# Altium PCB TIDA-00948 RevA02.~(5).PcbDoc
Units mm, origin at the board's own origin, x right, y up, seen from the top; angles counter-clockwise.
Board outline 125.73 x 87.63 mm, 2 copper layers (Top Layer, Bottom Layer), stack 1.575 mm thick; 30 components, 8 nets, 44 pads, 0 vias.
Unrouted connection lines stored in the file: 2.
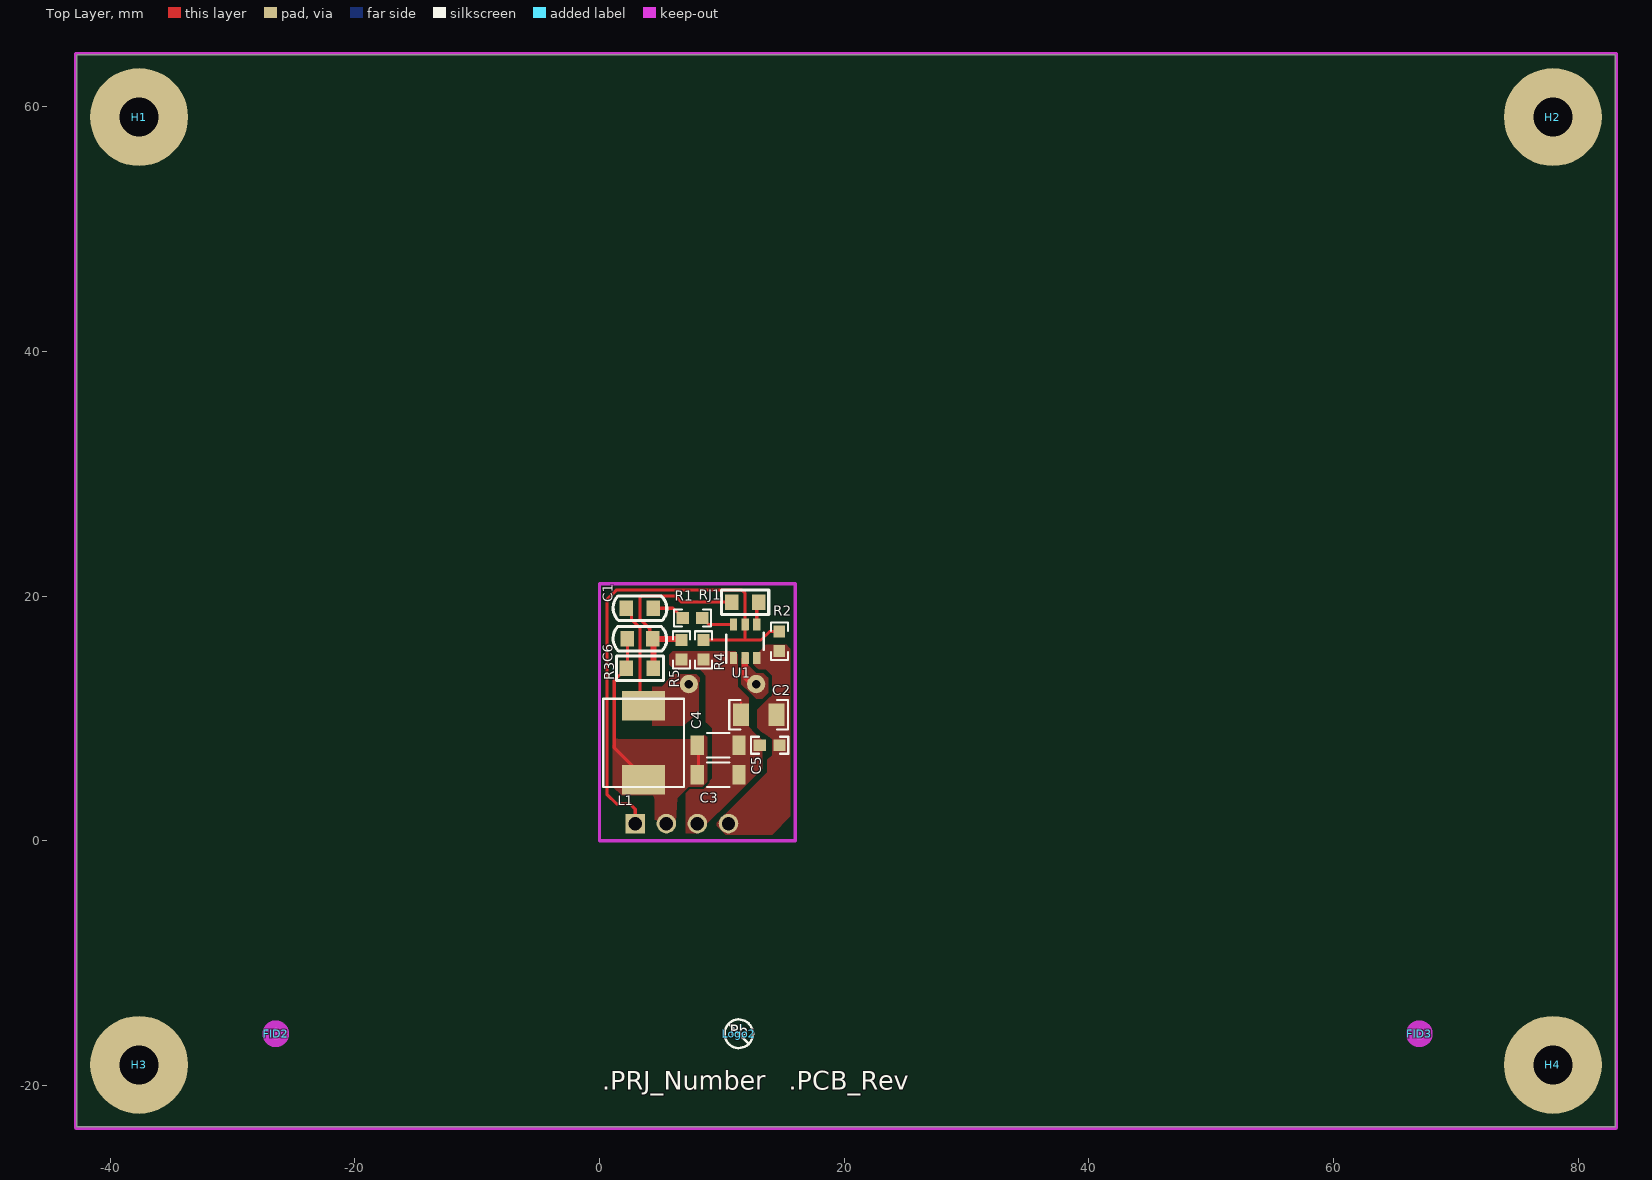
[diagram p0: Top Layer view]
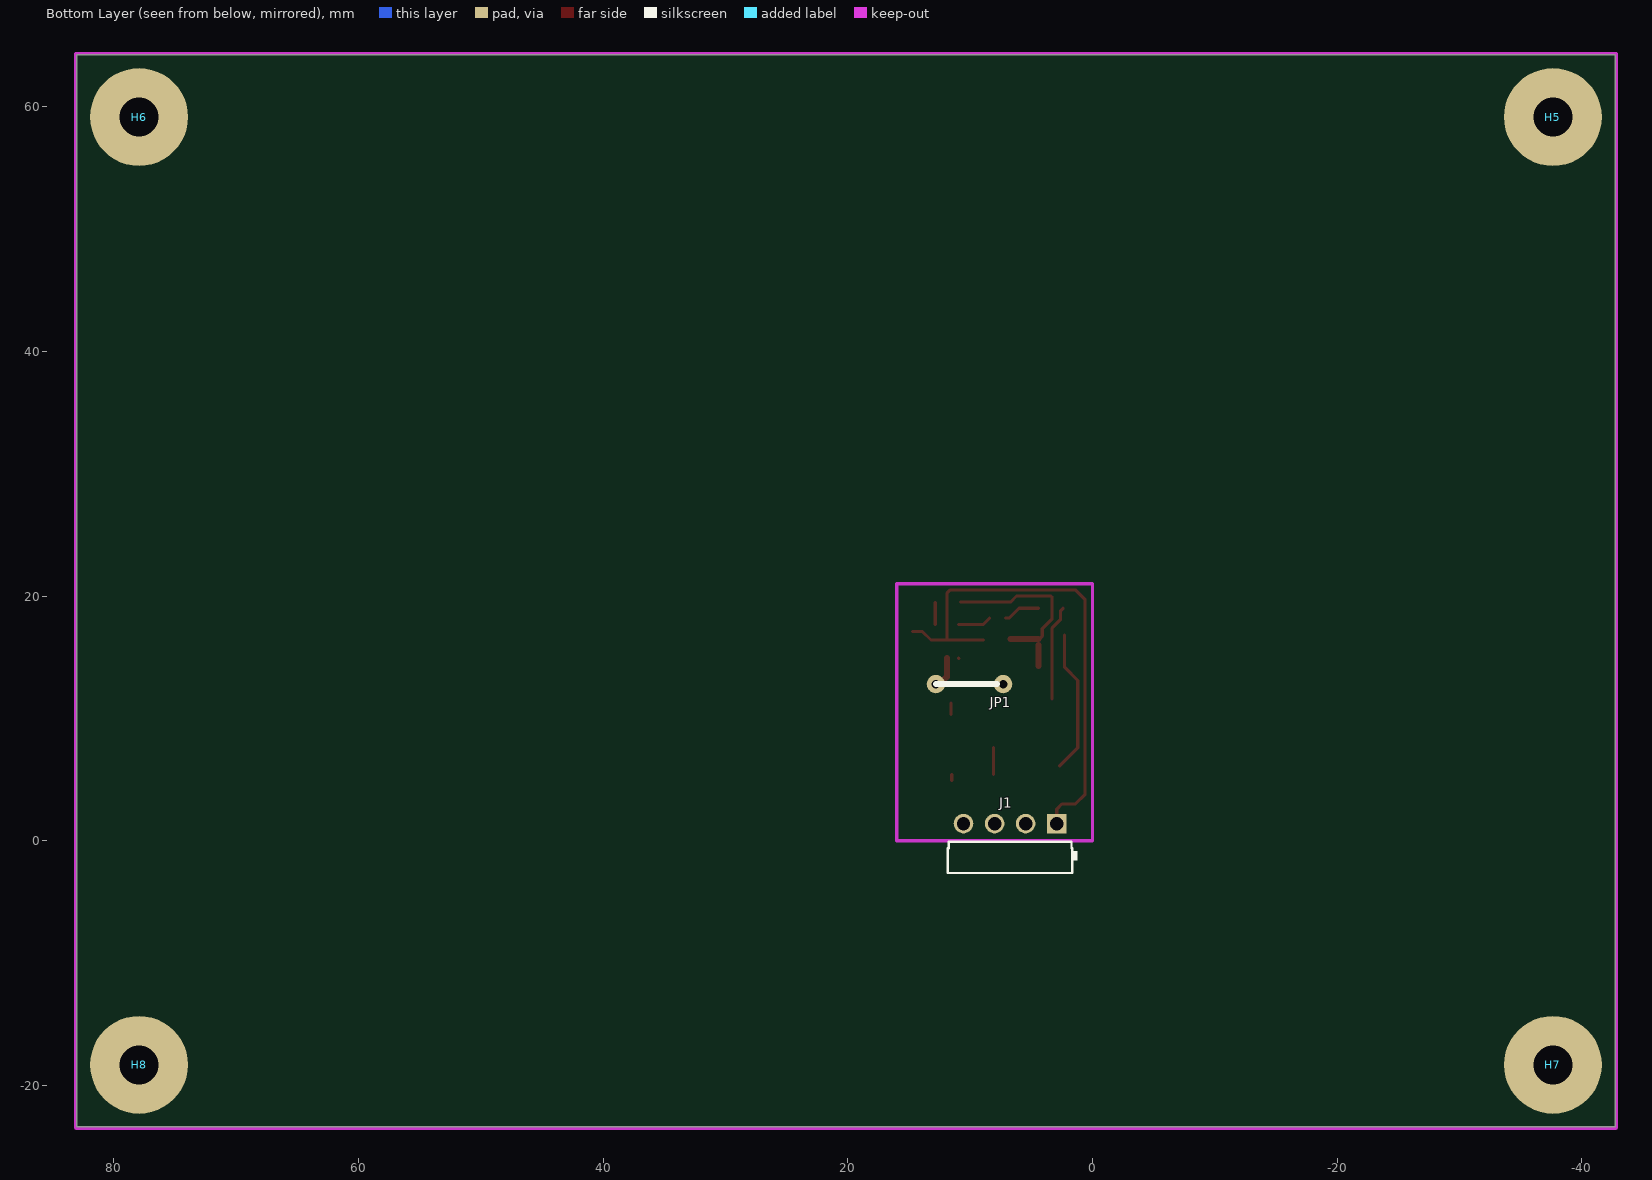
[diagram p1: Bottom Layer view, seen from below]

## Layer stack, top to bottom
Top Solder: solder mask 0.0102, Solder Resist, Dk 3.5
Top Layer: signal copper 0.0356
Dielectric1: core 1.5037, FR-4, Dk 4.8
Bottom Layer: signal copper 0.0356
Bottom Solder: solder mask 0.0102, Solder Resist, Dk 3.5

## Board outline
-42.72,-23.4 83.01,-23.4 83.01,64.23 -42.72,64.23

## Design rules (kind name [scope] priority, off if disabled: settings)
AcuteAngle [All] p1: minimum=4.50000000000000E+0001 checktracksonly=FALSE
AssemblyTestPointUsage [All] p1: valid=2
Clearance Clearance_Keepouts [((IsTrack Or IsArc) And Not InPoly) And IsFree and IsKeepOut vs ((IsTrack Or IsArc) And Not InPoly) And IsFree and IsKeepOut] p1 off: gap=0
Clearance Clearance_BoardEdge_MountingHoles [OnCopper and InComponentClass('Mounting Holes') vs IsKeepOut] p2 off: gap=1.016
Clearance Clearance_BoardEdge_Poly [OnCopper and InPoly vs IsKeepOut] p3 off: gap=0.635
Clearance Clearance_BoardEdge [OnCopper and Not InComponentClass('Logo') and not InComponentClass('FiducialMark') and not InRegion(1000,500,4000,800) and Not IsKeepout vs IsKeepOut] p4 off: gap=1.905
Clearance Clearance_Poly [InPolygon] p5 off: gap=0.635
Clearance [All] p6: gap=0.2
ComponentClearance ComponentClearance_MountingHoles_FiducialMarks [InComponentClass('Mounting Holes') vs InComponentClass('FiducialMark')] p1: gap=1.27 collisioncheckmode=3 verticalgap=0.254 showdistances=FALSE
ComponentClearance ComponentClearance_Shunt [InComponentClass('Header') vs InComponentClass('Shunt')] p2: gap=0 collisioncheckmode=3 verticalgap=0 showdistances=FALSE
ComponentClearance ComponentClearance_Logo [InComponentClass('Logo')] p3: gap=1.27 collisioncheckmode=3 verticalgap=0.254 showdistances=FALSE
ComponentClearance ComponentClearance_ScrewToNut [(HasFootprint('NY PMS 440 0025 PH')) vs (HasFootprint('Keystone_1902C'))] p4: gap=0.127 collisioncheckmode=3 verticalgap=0.254 showdistances=FALSE
ComponentClearance ComponentClearance_MountingHoles [InComponentClass('Mounting Holes')] p5: gap=6.35 collisioncheckmode=3 verticalgap=2540 showdistances=FALSE
ComponentClearance ComponentClearance_SmallPassives [HasFootprint('0201*') or HasFootprint('0402*') or HasFootprint('0508') or HasFootprint('0603*') or HasFootprint('0612') or HasFootprint('0805*') or HasFootprint('0815*') or HasFootprint('0830*') or HasFootprint('1206*') or HasFootprint('1210*') or HasFootprint('1808*') or HasFootprint('1812*') or HasFootprint('1825*') or HasFootprint('2010*') or HasFootprint('2220*') or HasFootprint('2225*') or HasFootprint('2512*') or HasFootprint('2728*') or HasFootprint('3518*') vs HasFootprint('0201*') or HasFootprint('0402*') or HasFootprint('0508') or HasFootprint('0603*') or HasFootprint('0612') or HasFootprint('0805*') or HasFootprint('0815*') or HasFootprint('0830*') or HasFootprint('1206*') or HasFootprint('1210*') or HasFootprint('1808*') or HasFootprint('1812*') or HasFootprint('1825*') or HasFootprint('2010*') or HasFootprint('2220*') or HasFootprint('2225*') or HasFootprint('2512*') or HasFootprint('2728*') or HasFootprint('3518*')] p6: gap=0.508 collisioncheckmode=3 verticalgap=0.254 showdistances=FALSE
ComponentClearance ComponentClearance_THtoSMT [IsThruComponent vs IsSMTComponent] p7: gap=2.54 collisioncheckmode=3 verticalgap=0.762 showdistances=FALSE
ComponentClearance ComponentClearance_THtoTH [IsThruComponent vs IsThruComponent] p8: gap=3 collisioncheckmode=3 verticalgap=0.762 showdistances=FALSE
ComponentClearance [All] p9: gap=1.016 collisioncheckmode=3 verticalgap=0.254 showdistances=FALSE
DiffPairsRouting [All] p1: maxlimit=2.54 minlimit=0.254 mostfreqgap=0.254 toplayer_minwidth=0.381 toplayer_maxwidth=0.381 toplayer_prefwidth=0.381 bottomlayer_minwidth=0.381 bottomlayer_maxwidth=0.381 bottomlayer_prefwidth=0.381 maxuncoupledlength=25.4
FabricationTestPointUsage TestPointUsage [All] p1: valid=2 allowmultiple=FALSE
FabricationTestpoint Testpoint [All] p1: side=3 testpointundercomponent=TRUE minsize=1.016 maxsize=2.54 preferedsize=1.524 minholesize=0 maxholesize=1.016 preferedholesize=0.813 testpointgrid=0.025 allowsidetop=TRUE allowsidebottom=TRUE usegrid=TRUE gridtolerance=0
FanoutControl Fanout_LCC [IsLCC] p1: bgadir=Out bgaviamode=Centered fanoutstyle=Auto fanoutdirection=Alternating viagrid=0.025 // Fanout_LCC (Default Rule)
FanoutControl Fanout_BGA [IsBGA] p2: bgadir=Out bgaviamode=Centered fanoutstyle=Auto fanoutdirection=Alternating viagrid=0.025 // Fanout_BGA (Default Rule)
FanoutControl Fanout_Default [All] p4: bgadir=Out bgaviamode=Centered fanoutstyle=Auto fanoutdirection=Alternating viagrid=0.025 // Fanout_Default (Default Rule)
FanoutControl Fanout_Small [(CompPinCount < 5)] p5: bgadir=Out bgaviamode=Centered fanoutstyle=Auto fanoutdirection=OutThenIn viagrid=0.025 // Fanout_Small (Default Rule)
HoleSize [All] p1: absolutevalues=TRUE maxlimit=6.375 minlimit=0.203 maxpercent=80.000 minpercent=20.000
MinimumAnnularRing MinimumAnnularRing_ThermalPadVias [IsVia and InAnyComponent] p1: minimumring=0.15
MinimumAnnularRing [All] p2: minimumring=0.229
MinimumSolderMaskSliver MinimumSolderMaskSliver_Logo [InComponentClass('Logo') vs InComponentClass('Logo')] p1: minsoldermaskwidth=0.018
MinimumSolderMaskSliver [All] p2: minsoldermaskwidth=0.1
PlaneConnect [All] p1: planeconnectstyle=Relief reliefexpansion=0.254 reliefentries=4 reliefconductorwidth=0.254 reliefairgap=0.254
PolygonConnect [All] p1: connectstyle=Direct reliefconductorwidth=0.254 reliefentries=4 polygonreliefangle="90 Angle" airgapwidth=0.254
RoutingVias ThermalPadVias [IsVia and InAnyComponent] p1: holewidth=0.2 width=0.5 viastyle="Through Hole" minholewidth=0.2 minwidth=0.5 maxholewidth=0.33 maxwidth=0.6
RoutingVias [All] p2: holewidth=0.406 width=0.864 viastyle="Through Hole" minholewidth=0.2 minwidth=0.66 maxholewidth=1.016 maxwidth=1.651
SilkToBoardRegionClearance [Not ((IsComment or IsDesignator) And (Hide <> 'False')) and not InRegion(1000,500,4000,800)] p1:
SilkToSilkClearance SilkToSilkClearance_Pb-FreeLogo [(HasFootprint('Pb-Free_Overlay_Medium') OR HasFootprint('Pb-Free_Overlay_Small')) vs (HasFootprint('Pb-Free_Overlay_Medium') OR HasFootprint('Pb-Free_Overlay_Small'))] p1: silktosilkclearance=0
SilkToSilkClearance [All] p2: silktosilkclearance=0.102
SilkToSolderMaskClearance SilkToComonentPadClearance [IsPad and InAnycomponent] p1: minsilkscreentomaskgap=0.127 clearancetoexposedcopper=TRUE
SilkToSolderMaskClearance "Silk to Solder Mask Opening" [All] p2: minsilkscreentomaskgap=0.102 clearancetoexposedcopper=FALSE
SolderMaskExpansion [All] p1: expansion=0.05
UnpouredPolygon [All] p1: allowunpoured=FALSE
Width [All] p1: maxlimit=2.54 minlimit=0.152 preferedwidth=0.254 checkconnectedcopper=TRUE
14 further rules are at their usual default settings.

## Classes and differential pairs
component class "Mounting Holes": H1 H2 H3 H4
component class TID_Hardware: FID2 FID3 H1 H2 H3 H4 H5 H6 H7 H8 Logo2 ZZ2 ZZ3 ZZ4
component class FiducialMark: FID2 FID3
component class AssemblyNote: ZZ2 ZZ3 ZZ4
component class Header: JP1
component class "TIDA-00948 RevA": C1 C2 C3 C4 C5 C6 JP1 L1 R1 R2 R3 R4 R5 U1

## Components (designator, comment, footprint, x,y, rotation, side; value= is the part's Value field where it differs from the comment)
C1 "GRM188R71E104KA01D" C/0805/SMT1#1 4.3,19 r180 top
C2 "GRM31CR71E106KA12L" 1206 13,10.3 r180 top
C3 "GCM31CR71A226KE02" 1206_190 9.7,5.4 r0 top
C4 "GCM31CR71A226KE02" 1206_190 9.7,7.8 r0 top
C5 "GRM188R71E104KA01D" 0603 13.9,7.8 r180 top
C6 "06033C101KAT2A" C/0805/SMT1#2 2.3,16.5 r0 top
FID2 "Fiducial" Fiducial10-20 -26.464,-15.78 r0 top
FID3 "Fiducial" Fiducial10-20 67.008,-15.78 r0 top
H1 "NY PMS 440 0025 PH" "NY PMS 440 0025 PH" -37.64,59.15 r0 top locked
H2 "NY PMS 440 0025 PH" "NY PMS 440 0025 PH" 77.93,59.15 r0 top locked
H3 "NY PMS 440 0025 PH" "NY PMS 440 0025 PH" -37.64,-18.32 r0 top locked
H4 "NY PMS 440 0025 PH" "NY PMS 440 0025 PH" 77.93,-18.32 r0 top locked
H5 "1902C" Keystone_1902C -37.64,59.15 r180 bottom locked
H6 "1902C" Keystone_1902C 77.93,59.15 r180 bottom locked
H7 "1902C" Keystone_1902C -37.64,-18.32 r180 bottom locked
H8 "1902C" Keystone_1902C 77.93,-18.32 r180 bottom locked
J1 "61300411021" Wurth_61300411021 6.73,1.4 r0 bottom
JP1 "Comment" JUMP-5 7.8,12.8 r0 bottom
L1 "LPS8045B-333MRB" WE-PD-M 3.6,8 r270 top
Logo2 "Pb-Free Symbol" Pb-Free_Overlay_Small 11.382,-15.78 r0 top
R1 "CRCW06030000Z0EA" 0603 7.6,18.2 r180 top
R2 "CRCW0603510KJNEA" 0603 14.7,16.3 r270 top
R3 "CRCW0603100KFKEA" R/0805/SMT1 3.3,14.1 r180 top
R4 "CRCW0603105KFKEA" 0603 8.5,15.6 r90 top
R5 "CRCW060313K3FKEA" 0603 6.7,15.6 r90 top
RJ1 "Comment" R/0805/SMT1 11.9,19.5 r0 top
U1 "TPS54202DDCR" DDC0006A_N 11.9,16.3 r90 top
ZZ2 "These assemblies are ESD sensitive, ESD precautions shall be observed." AssemblyNote -38.021,73.859 r0 top
ZZ3 "These assemblies must be clean and free from flux and all contaminants. Use of no clean flux is not acceptable." AssemblyNote -38.021,71.61 r0 top
ZZ4 "These assemblies must comply with workmanship standards IPC-A-610 Class 2, unless otherwise specified." AssemblyNote -38.021,69.361 r0 top

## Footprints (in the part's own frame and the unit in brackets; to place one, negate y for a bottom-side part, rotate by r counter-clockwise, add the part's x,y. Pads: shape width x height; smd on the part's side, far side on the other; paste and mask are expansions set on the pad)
0603 [mm] "0603 from SM-752 data"
  rect 1x0.95 smd: 1(-0.8,0) 2(0.8,0)
  silkscreen extent -1.52,-0.69 1.52,0.69, body extent -0.87,-0.47 0.87,0.47, height 1
1206 [mm] "1206 from SM-752 data"
  rect 1.3x1.85 smd: 1(-1.45,0) 2(1.45,0)
  silkscreen extent -2.4,-1.21 2.4,1.21, body extent -1.7,-0.9 1.7,0.9, height 1.35
1206_190 [mm] "1206_190"
  rect 1.1x1.6 smd: 1(-1.7,0) 2(1.7,0)
  silkscreen extent -0.9,-1 0.9,1, body extent -1.75,-0.95 1.75,0.95, height 1.9
AssemblyNote [mm] "Assembly Note"
C/0805/SMT1#1 [mm]
  rect 1.1x1.25 smd: 1(-0.1,0) 2(2.1,0)
  silkscreen extent -1.19,-1 3.19,1.01
C/0805/SMT1#2 [mm]
  rect 1.1x1.25 smd: 1(-0.05,0) 2(2.05,0)
  silkscreen extent -1.19,-1 3.19,1.01
DDC0006A_N [mm]
  rrect17% 1x0.6 smd: 1(-1.375,0.95) 2(-1.375,0) 3(-1.375,-0.95) 4(1.375,-0.95) 5(1.375,0) 6(1.375,0.95)
  silkscreen extent -1.75,-1.52 0.7,1.53, body extent -1.43,-1.48 1.43,1.49, height 0.92
Fiducial10-20 [mm]
  round 1 smd mask+0.5: 1(0,0)
  Top Layer keep-out circle w1.178: c0,0 r0.5
JUMP-5 [mm]
  round 1.5 hole 0.7: 1(-0.5,0) 2(5,0)
  silkscreen extent 0,0 5,0
Keystone_1902C [mm] "Hex Standoff, 4-40 threaded, nylon"
  body extent -3.68,-3.2 3.71,3.2, height 12.73
"NY PMS 440 0025 PH" [mm] "4-40 nylon screw and mounting hole"
  round 8 hole 3.2: 1(0,0)
  body extent -3.3,-3.3 3.3,3.3, height 2.69
Pb-Free_Overlay_Small [mm]
  silkscreen extent -1.16,-1.17 1.17,1.17
R/0805/SMT1 [mm]
  rect 1.1x1.25 smd: 1(-1.1,0) 2(1.1,0)
  silkscreen extent -1.92,-1 1.93,1
WE-PD-M [mm] "Wurth Elektronik recommended land pattern, 2008-01-04"
  rect 2.4x3.5 smd: 1(-3.035,0) 2(3.004,0)
  silkscreen extent -3.6,-3.3 3.6,3.3, body extent -3.81,-3.84 3.81,3.79, height 4.5
Wurth_61300411021 [mm] "Header, 2.54 mm, 4x1, R/A, TH"
  rect 1.6x1.6 hole 1.1: 1(-3.81,0)
  round 1.6 hole 1.1: 2(-1.27,0) 3(1.27,0) 4(3.81,0)
  silkscreen extent -5.5,1.5 5.08,4.04, body extent -5.08,-0.32 5.08,10.04, height 5.55

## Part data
C1 C5: "CAP, CERM, 0.1 μF, 25 V, +/- 10%, X7R, 0603"
C2: "CAP, CERM, 10 μF, 25 V, +/- 10%, X7R, 1206"
C3 C4: "CAP, CERM, 22 μF, 10 V, +/- 10%, X7R, AEC-Q200 Grade 1, 1206_190"
C6: "CAP, CERM, 100 pF, 25 V, +/- 10%, X7R, 0603"
FID2 FID3: "Fiducial mark.  There is nothing to buy or mount."
H1 H2 H3 H4: "Machine Screw, Round, #4-40 x 1/4, Nylon, Philips panhead"
H5 H6 H7 H8: "Standoff, Hex, 0.5\"L #4-40 Nylon"
J1: "Header, 2.54 mm, 4x1, Gold, R/A, TH"
L1: "Inductor, Shielded, Ferrite, 33 μH, 1.2 A, 0.121 ohm, SMD"
Logo2: library part Pb-Free
R1: "RES, 0, 5%, 0.1 W, 0603"
R2: "RES, 510 k, 5%, 0.1 W, 0603"
R3: "RES, 100 k, 1%, 0.1 W, 0603"
R4: "RES, 105 k, 1%, 0.1 W, 0603"
R5: "RES, 13.3 k, 1%, 0.1 W, 0603"
U1: "4.5-V TO 28-V INPUT, 2-A OUTPUT, EMI FRIENDLY SYNCHRONUOUS STEP-DOWN CONVERTOR, DDC0006A"
ZZ2 ZZ3 ZZ4: library part AssemblyNote

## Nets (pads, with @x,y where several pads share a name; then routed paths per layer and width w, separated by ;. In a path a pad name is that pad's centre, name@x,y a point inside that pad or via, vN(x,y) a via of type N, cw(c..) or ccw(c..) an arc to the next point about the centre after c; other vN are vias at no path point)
+5V: C3.1 C4.1 C6.1 J1.2 L1.2 R3.2 | length 14
  Top Layer w0.254: C6.1@2.278,16.8 2.278,14.178 1.2,13.1 1.2,7.6 L1.2@2.703,6.097 ; C3.1@8.1,5.4 C4.1@8.1,7.6
EN: J1.1 R2.1 R4.2 U1.5 | length 41.6
  Top Layer w0.254: J1.1 2.92,2.58 2.5,3 1.4,3 0.6,3.8 0.6,19.7 1.4,20.5 11.619,20.5 11.9,20.219 U1.5 11.9,16.5 11.8,16.4 ; R4.2@8.9,16.4 11.8,16.4 ; R2.1 13.9,17.1 13.2,16.4 11.8,16.4
GND: C2.2 C3.2 C4.2 C5.2 J1.3 R4.1 R5.1 U1.1 | length 1.5
  Top Layer w0.254: U1.1@10.925,14.9 U1.1 ; C3.2@11.5,4.912 C3.2@11.5,5.4 ; C2.2 11.55,11.25
NetC1_1: C1.1 R1.2 | length 3
  Top Layer w0.254: C1.1 6,19 R1.2 R1.2@7.1,18.2
NetC1_2: C1.2 JP1.1 JP1.2 L1.1 U1.2 | length 10.1
  Top Layer w0.254: C1.2@2.4,19 2.6,18.8 2.6,18.1 3.3,17.4 L1.1@3.3,11.603
  Top Layer w0.5: U1.2 11.9,13.4 JP1.2@12.5,12.8
NetC6_2: C6.2 R3.1 R5.2 RJ1.1 RJ1.2 U1.4 | length 17.4
  Top Layer w0.254: C6.2@4.4,16.5 4.322,16.5 4.1,16.722 4.1,17.338 3.3,18.138 3.3,19.9 3.395,19.995 6.205,19.995 6.7,19.5 RJ1.1@10.778,19.5 ; U1.4 RJ1.2@12.85,19.472
  Top Layer w0.5: R3.1@4.4,14.3 C6.2@4.4,16 ; C6.2@4.4,16.5 R5.2@6.7,16.5
NetR1_1: R1.1 U1.6 | length 2.8
  Top Layer w0.254: R1.1 8.925,17.675 U1.6
VIN: C2.1 C5.1 J1.4 R2.2 U1.3
pads on no net: FID2.1 FID3.1 H1.1 H2.1 H3.1 H4.1

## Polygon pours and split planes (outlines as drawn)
+5V on Top Layer "Top Layer-No Net 4" (solid, remove dead copper, pour order 10): 8.8,8.7 8.8,4.8 8.4,4.4 7.3,4.4 6.35,3.45 6.221,1.547 5.278,1.435 4.5,1.72 4.5,3.4 4.4,3.7 1.8,3.7 1.1,4.4 1.1,7.8 1.2,7.9 1.2,8.6 1.5,8.3 7.5,8.3
NetC1_2 on Top Layer "Top Layer-No Net 3" (solid, remove dead copper, pour order 8): 12.1,14.9 12.1,14.4 12.4,14.1 12.8,13.7 13.2,13.7 13.4,13.7 13.6,13.5 13.8,13.3 13.8,12.7 13.8,12.1 13.5,11.8 13.3,11.6 12.9,11.6 12.8,11.6 12.3,12.1 11.6,12.8 11.6,14 11.6,14.9
NetC1_2 on Top Layer "Top Layer-No Net 2" (solid, remove dead copper, pour order 6): 8.1,13 8.1,10.6 7.6,10.1 6.9,9.4 3.1,9.4 2.2,9.4 1.8,9.8 1.8,12.4 2,12.6 4.4,12.6 5.1,12.6 5.8,13.3 6.1,13.6 7.8,13.6 7.9,13.6 8.2,13.3 8.2,12.4
VIN on Top Layer "Top Layer-No Net 1" (solid, remove dead copper, pour order 4): 12.6,15.1 12.6,14.4 12.9,14.1 13,14 13.5,14 13.6,14 14,13.6 14.1,13.5 14.1,12.4 14.1,11.9 13.8,11.6 12.9,10.7 12.9,10 12.9,9.223 13.211,8.912 13.615,8.679 14.1,8.3 14.1,7.8 14.1,7 13.7,6.6 13.7,5.6 9.45,1.35 10.3,0.5 14.1,0.5 15.6,2 15.6,8.3 15.6,15.7 15.4,15.9 15.3,16 14.2,16 13.6,16 13,15.4
GND on Top Layer "Top Layer-No Net" (solid, remove dead copper, pour order 2): 11.135,15.397 11.3,15.232 11.3,12.8 11.3,12.6 11.8,12.1 12.2,11.7 12.2,10.8 12.2,9.3 12.7,8.8 13.3,8.2 13.3,6.2 13.3,5.9 11.4,4 8,0.6 7.049,0.6 7.049,4.049 7.6,4.6 8.633,4.6 9.2,5.087 9.2,9.2 8.9,9.5 8.7,9.7 8.7,13.2 8.7,13.5 8.4,13.8 8.2,14 7,14 6.1,14 5.7,14.4 5.7,15.2 5.972,15.472 11.135,15.472
VIN on Top Solder "Top Solder-No Net" (hatched 90Degree grid 0.2 track 0.203, remove dead copper): 9.8,1.5 13.7,5.4 13.7,6.2 15.3,6.2 15.5,6 15.5,2.2 14.9,1.6 13.9,0.6 10.6,0.6
no net on Top Solder "Top Solder-No Net" (hatched 90Degree grid 0.2 track 0.203, remove dead copper): 9,13.4 10.9,13.4 11.1,13.2 11.1,12.4 11.1,9.7 10.8,9.4 9.3,9.4 9.1,9.6 8.9,9.8 8.9,12.6

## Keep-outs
Keep-Out Layer:
  lines w0.254: -42.847,-23.4 ccw(c-42.72,-23.4) -42.72,-23.527 ; -42.847,-23.4 ccw(c-42.72,-23.4) -42.72,-23.527 ; -42.847,-23.4 -42.847,64.23 ; -42.847,64.23 cw(c-42.72,64.23) -42.72,64.357 ; -42.847,64.23 cw(c-42.72,64.23) -42.72,64.357 ; -42.72,-23.527 83.01,-23.527 ; -42.72,64.357 83.01,64.357 ; 83.01,-23.527 ccw(c83.01,-23.4) 83.137,-23.4 ; 83.01,-23.527 ccw(c83.01,-23.4) 83.137,-23.4 ; 83.01,64.357 cw(c83.01,64.23) 83.137,64.23 ; 83.01,64.357 cw(c83.01,64.23) 83.137,64.23 ; 83.137,-23.4 83.137,64.23 ; 0,0 16,0 16,21 0,21 0,0
  text ".Layer_Name" at -28.064,-45.206 h1.52

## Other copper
Top Layer:
  text ".Layer_Name" at -28.064,-45.206 h1.52
Bottom Layer:
  text ".Layer_Name" at -28.064,-45.206 h1.52

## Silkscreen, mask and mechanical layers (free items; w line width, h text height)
Top Overlay:
  text ".PRJ_Number" at 0.206,-20.352 h1.52
  text ".PCB_Rev" at 15.446,-20.352 h1.52
  text ".Layer_Name" at -28.064,-45.206 h1.52
Bottom Overlay:
  text ".Layer_Name" at -28.064,-45.206 h1.52
Top Paste:
  text ".Layer_Name" at -28.064,-45.206 h1.52
Bottom Paste:
  text ".Layer_Name" at -28.064,-45.206 h1.52
Top Solder:
  text ".Layer_Name" at -28.064,-45.206 h1.52
  text ".Layer_Name" at -28.064,-45.206 h1.52
Bottom Solder:
  text ".Layer_Name" at -28.064,-45.206 h1.52
Drill Guide:
  text ".Layer_Name" at -28.064,-45.206 h1.52
M1 Board Outline:
  the board outline again, w0.254
  text ".Layer_Name" at -28.064,-45.206 h1.52
M2 Board Dimensions:
  rectangle: -42.72,-30.385 -39.545,-27.21
  rectangle: -39.545,-33.56 -30.02,-30.385
  lines w0.178: -42.72,-30.385 -17.32,-30.385 ; -39.545,-33.56 -39.545,-27.21 ; -36.37,-33.56 -36.37,-27.21 ; -30.02,-33.56 -30.02,-27.21 ; -23.67,-33.56 -23.67,-27.21 ; -42.72,-33.56 -17.32,-33.56 -17.32,-27.21 -42.72,-27.21 -42.72,-33.56
  text ".Layer_Name" at -28.064,-45.206 h1.52
M3 3D STEP Top:
  text ".Layer_Name" at -28.064,-45.206 h1.52
M4 3D STEP Bottom:
  text ".Layer_Name" at -28.064,-45.206 h1.52
M5 Assembly Top:
  lines w0.254: -50.137,-47.026 117.503,-47.026 ; -50.137,-41.862 117.554,-41.862 ; -50.137,-36.697 -50.137,-52.191 51.59,-52.191 117.554,-52.191 117.554,-36.697 -50.124,-36.697 -50.124,-52.191 -10.106,-52.191 ; 12.474,-52.191 12.474,-36.697 ; 44.656,-41.862 44.656,-36.697 ; 65.992,-41.862 65.992,-36.697 ; 81.791,-52.356 81.791,-47.204
  text "COMPONENTS MARKED 'DNP' SHOULD NOT BE POPULATED." at -13.421,-31.49 h1.52
  text "ASSEMBLY VARIANT:" at -13.434,-34.424 h1.52
  text ".VariantName" at 12.881,-34.424 h1.52
  text "PCB VIEWED FROM TOP SIDE" at -48.524,-40.054 h1.52
  text "BOARD #:" at 14.379,-40.054 h1.52
  text ".PRJ_Number" at 28.235,-40.054 h1.52
  text "REV:" at 49.685,-40.054 h1.52
  text ".PCB_Rev" at 57.089,-40.054 h1.52
  text "SVN REV:" at 70.97,-40.054 h1.52
  text ".VersionControl_RevNumber" at 83.823,-40.054 h1.52
  text "TID #:" at 14.379,-45.219 h1.52
  text ".TID" at 28.235,-45.219 h1.52
  text "PLOT NAME =" at -48.524,-50.434 h1.52
  text ".plot_File_Name" at -28.064,-50.434 h1.52
  text "GENERATED    :" at 14.43,-50.434 h1.52
  text ".Print_Date" at 36.515,-50.434 h1.52
  text ".Print_Time" at 55.032,-50.434 h1.52
  text "TEXAS INSTRUMENTS" at 87.15,-50.434 h1.52
M6 Assembly Bottom:
  lines w0.254: -50.15,-41.874 117.541,-41.874 ; -50.099,-47.039 117.541,-47.039 ; -14.386,-52.369 -14.386,-47.217 ; 1.412,-41.874 1.412,-36.71 ; 22.748,-41.874 22.748,-36.71 ; 54.93,-52.204 54.93,-36.71 ; 77.511,-52.204 117.529,-52.204 117.529,-36.71 -50.15,-36.71 -50.15,-52.204 15.814,-52.204 117.541,-52.204 117.541,-36.71
  text "COMPONENTS MARKED 'DNP' SHOULD NOT BE POPULATED." at 112.271,-31.477 h1.52
  text ".VariantName" at 85.753,-34.424 h1.52
  text "ASSEMBLY VARIANT:" at 112.144,-34.424 h1.52
  text ".VersionControl_RevNumber" at -16.418,-40.067 h1.52
  text "SVN REV:" at -3.566,-40.067 h1.52
  text ".PCB_Rev" at 10.315,-40.067 h1.52
  text "REV:" at 17.719,-40.067 h1.52
  text ".PRJ_Number" at 39.17,-40.067 h1.52
  text "BOARD #:" at 53.025,-40.067 h1.52
  text "PCB VIEWED FROM BOTTOM SIDE" at 115.928,-40.067 h1.52
  text ".TID" at 39.17,-45.231 h1.52
  text "TID #:" at 53.025,-45.231 h1.52
  text "TEXAS INSTRUMENTS" at -19.746,-50.447 h1.52
  text ".Print_Time" at 12.373,-50.447 h1.52
  text ".Print_Date" at 30.889,-50.447 h1.52
  text "GENERATED    :" at 52.974,-50.447 h1.52
  text ".plot_File_Name" at 95.469,-50.447 h1.52
  text "PLOT NAME =" at 115.928,-50.447 h1.52
M9 Title Sheet:
  drawing of 57 lines, arcs and shapes, not listed
  text "1" at -23.928,180.727 h1.78
  text "2" at 39.462,180.727 h1.78
  text "3" at 102.691,180.727 h1.78
  text "4" at 166.36,180.727 h1.78
  text "5" at 229.835,180.727 h1.78
  text "6" at 293.462,180.727 h1.78
  text "A" at -53.299,151.695 h1.78
  text "A" at 322.621,151.695 h1.78
  text "B" at -53.299,91.243 h1.78
  text "B" at 322.621,91.243 h1.78
  text "C" at -53.299,30.918 h1.78
  text "C" at 322.621,30.918 h1.78
  text "PROJECT TITLE:" at 245.405,-16.351 h1.14
  text ".PRJ_Title" at 246.675,-19.738 h1.78
  text "DESIGNED FOR:" at 245.405,-23.997 h1.14
  text ".PRJ_Customer" at 246.675,-27.553 h1.78
  text "D" at -53.299,-29.28 h1.78
  text "D" at 322.621,-29.28 h1.78
  text "FILE NAME:" at 245.405,-31.617 h1.14
  text ".PCB_File_Name_No_Path" at 246.675,-34.665 h1.78
  text "Texas Instruments (TI) and/or its licensors do not warrant the accuracy or completeness of this specification" at 119.18,-38.776 h1.14
  text "ENGINEER:" at 245.405,-38.983 h1.14
  text "LAYOUT BY:" at 283.632,-38.983 h1.14
  text "or any information contained therein. TI and/or its licensors do not warrant that this design will meet" at 118.037,-41.637 h1.14
  text ".PRJ_Engineer" at 246.675,-42.92 h1.78
  text ".PCB_Layout" at 284.915,-42.92 h1.78
  text "the specifications, will be suitable for your application or fit for any particular purpose, or will operate in" at 118.037,-44.499 h1.14
  text ".Layer_Name" at -28.064,-45.206 h1.52
  text "ALTIUM DESIGNER VERSION:" at 283.632,-46.857 h1.14
  text "an implementation. TI and/or its licensors do not warrant that the design is production worthy. You should" at 118.037,-47.361 h1.14
  text "completely validate and test your design implementation to confirm the system functionality for your application." at 119.18,-50.222 h1.14
  text ".print_Scale" at 246.675,-50.243 h1.78
  text ".Application_BuildNumber" at 284.915,-50.243 h1.78
  text "1" at -23.928,-55.493 h1.78
  text "2" at 39.462,-55.493 h1.78
  text "3" at 102.691,-55.493 h1.78
  text "4" at 166.36,-55.493 h1.78
  text "5" at 229.835,-55.493 h1.78
  text "6" at 293.462,-55.493 h1.78
M10 Fab Notes:
  drawing of 173 lines, arcs and shapes, not listed
  text "DESIGN INFORMATION" at 271.656,134.105 h1.52
  text "MIN. TRACK WIDTH:" at 255.284,129.533 h1.52
  text "8" at 283.129,129.533 h1.52
  text "MIL" at 287.06,129.533 h1.52
  text "MIN. CLEARANCE:" at 255.284,126.181 h1.52
  text "0.2" at 281.605,126.181 h1.52
  text "mm" at 287.06,126.181 h1.52
  text "MIN. VIA PAD SIZE:" at 255.284,122.828 h1.52
  text "24" at 282.367,122.828 h1.52
  text "MIL" at 287.06,122.828 h1.52
  text "0.05mm (2MIL)" at 272.937,119.228 h1.52
  text "MINIMUM ANNULAR RING" at 246.922,119.12 h1.52
  text "EXTERNAL" at 290.921,119.12 h1.52
  text "PER" at 252.002,116.122 h1.52
  text "IPC-D-275 CLASS 2 LEVEL C" at 257.59,116.122 h1.52
  text "MIL, HOLES" at 295.391,113.27 h1.52
  text "+/-" at 285.423,113.252 h1.52
  text "+/-" at 307.114,113.252 h1.52
  text "REGISTRATION TOLERANCES:" at 246.922,113.125 h1.52
  text "METAL" at 277.396,113.125 h1.52
  text "5" at 292.032,113.125 h1.52
  text "3" at 313.19,113.125 h1.52
  text "MIL" at 316.143,113.125 h1.52
  text "+/-" at 307.114,110.255 h1.52
  text "HOLE SIZE TOLERANCE (UNLESS OTHERWISE SPECIFIED):" at 246.922,110.128 h1.52
  text "3" at 313.19,110.128 h1.52
  text "MIL" at 316.143,110.128 h1.52
  text "MATERIAL:" at 245.023,104.808 h1.52
  text "FR-4 High Tg" at 270.079,101.243 h1.52
  text "FR-408" at 255.716,101.025 h1.52
  text "OTHER" at 293.511,101.025 h1.52
  text "X" at 266.144,100.933 h1.52
  text "62 MIL (1.6mm) +/-10%" at 263.847,96.892 h1.52
  text "THICKNESS:" at 246.922,96.784 h1.52
  text "X" at 260.591,96.784 h1.52
  text "OTHER" at 296.483,96.784 h1.52
  text "TOLERANCE:" at 246.922,92.77 h1.52
  text "X" at 268.24,92.77 h1.52
  text "ANSI IPC-6012 TYPE 3 CLASS 2" at 272.989,92.77 h1.52
  text "OTHER +/-" at 272.988,88.808 h1.52
  text "BOW & TWIST:" at 246.922,84.82 h1.52
  text "X" at 268.24,84.82 h1.52
  text "ANSI IPC-6012 TYPE 3 CLASS 2" at 272.989,84.82 h1.52
  text "OTHER +/-" at 272.988,80.794 h1.52
  text "DRILLING:" at 245.023,77.276 h1.52
  text "REFERENCE:" at 246.922,74.305 h1.52
  text "X" at 263.387,74.305 h1.52
  text "AS SHOWN" at 268.137,74.305 h1.52
  text "X" at 286.272,74.305 h1.52
  text "NC_DRILL FILES" at 289.752,74.305 h1.52
  text "PTH MIN COPPER THICKNESS:" at 246.922,70.291 h1.52
  text "X" at 281.218,70.291 h1.52
  text "1MIL" at 284.698,70.291 h1.52
  text "OTHER" at 297.321,70.291 h1.52
  text "BOARD FINISH:" at 245.023,66.253 h1.52
  text "SILKSCREEN:" at 248.965,63.256 h1.52
  text "X" at 273.064,63.256 h1.52
  text "TOP" at 276.265,63.256 h1.52
  text "X" at 286.018,63.256 h1.52
  text "BOTTOM" at 289.244,63.256 h1.52
  text "SILKSCREEN COLOR:" at 248.965,59.014 h1.52
  text "X" at 273.038,59.014 h1.52
  text "WHITE" at 276.265,59.014 h1.52
  text "OTHER" at 289.244,59.014 h1.52
  text "X" at 276.366,54.97 h1.52
  text "GREEN" at 279.592,54.97 h1.52
  text "OTHER" at 295.289,54.97 h1.52
  text "SOLDER RESIST COLOR:" at 248.965,54.696 h1.52
  text "X" at 276.366,50.652 h1.52
  text "MATTE" at 279.592,50.652 h1.52
  text "SEMI-GLOSS" at 295.278,50.636 h1.52
  text "IMMERSION GOLD (ENIG)" at 271.972,45.864 h1.52
  text "ENEPIG" at 305.946,45.78 h1.52
  text "SURFACE FINISH:" at 245.023,45.755 h1.52
  text "X" at 267.224,45.755 h1.52
  text "IMM. TIN/SILVER OR EQUIV" at 253.393,41.767 h1.52
  text "OTHER" at 289.752,41.767 h1.52
  text "ARRAY/PANEL:" at 245.023,37.221 h1.52
  text "CUT AND TRIM PER M1 BOARD OUTLINE" at 271.972,37.112 h1.52
  text "N.C. ROUTE" at 271.972,33.258 h1.52
  text "X" at 289.219,33.258 h1.52
  text "V. SCORE" at 293.969,33.258 h1.52
  text "CERTIFICATION:" at 245.023,29.778 h1.52
  text "MATERIALS AND WORKMANSHIP FOR ALL PCBS" at 263.438,29.778 h1.52
  text "TO MEET OR EXCEED THE REQUIREMENTS OF:" at 263.438,27.289 h1.52
  text "X" at 253.951,23.822 h1.52
  text "ANSI IPC-A-600F CLASS ->" at 257.482,23.822 h1.52
  text "X" at 299.114,23.822 h1.52
  text "2" at 302.135,23.822 h1.52
  text "1" at 294.134,23.784 h1.52
  text "3" at 311.126,23.784 h1.52
  text "X" at 274.628,19.771 h1.52
  text "RoHS" at 278.106,19.771 h1.52
  text "OTHER" at 294.474,19.771 h1.52
  text "PER ORDER" at 304.56,19.771 h1.52
  text "ALL BOARDS MUST MEET OR EXCEED UL94-V0 REQUIREMENTS." at 245.722,15.564 h1.52
  text "PCB MUST BEAR THE UL94V-0 UL REGISTERED MATERIAL ID NUMBER" at 245.722,12.516 h1.52
  text "ADDITIONAL REQUIREMENTS:" at 245.023,8.112 h1.52
  text "MICROSECTION:" at 246.922,5.191 h1.52
  text "YES" at 269.928,5.191 h1.52
  text "REQUIRED" at 291.81,1.225 h1.52
  text "BARE BOARD ELEC. TEST:" at 246.922,1.153 h1.52
  text "NONE" at 280.088,1.153 h1.52
  text "X" at 288.584,1.153 h1.52
  text "PER ORDER" at 306.846,1.153 h1.52
  text ".Layer_Name" at -28.064,-45.206 h1.52
M11 Gerber Information:
  lines w0.254: -50.137,-47.026 117.503,-47.026 ; -50.137,-41.862 117.554,-41.862 ; -50.137,-36.697 -50.137,-52.191 51.59,-52.191 117.554,-52.191 117.554,-36.697 -50.124,-36.697 -50.124,-52.191 -10.106,-52.191 ; 12.474,-52.191 12.474,-36.697 ; 44.656,-41.862 44.656,-36.697 ; 65.992,-41.862 65.992,-36.697 ; 81.791,-52.356 81.791,-47.204
  text "ALL ARTWORK VIEWED FROM TOP SIDE" at -48.524,-40.054 h1.52
  text "BOARD #:" at 14.379,-40.054 h1.52
  text ".PRJ_Number" at 28.235,-40.054 h1.52
  text "REV:" at 49.685,-40.054 h1.52
  text ".PCB_Rev" at 57.089,-40.054 h1.52
  text "SVN REV:" at 70.97,-40.054 h1.52
  text ".VersionControl_RevNumber" at 83.823,-40.054 h1.52
  text "LAYER NAME =" at -48.524,-45.206 h1.52
  text "TID #:" at 14.379,-45.219 h1.52
  text ".TID" at 28.235,-45.219 h1.52
  text "PLOT NAME =" at -48.524,-50.434 h1.52
  text ".plot_File_Name" at -28.064,-50.434 h1.52
  text "GENERATED    :" at 14.43,-50.434 h1.52
  text ".Print_Date" at 36.515,-50.434 h1.52
  text ".Print_Time" at 55.032,-50.434 h1.52
  text "TEXAS INSTRUMENTS" at 87.15,-50.434 h1.52
M12 Stackup:
  drawing of 191 lines, arcs and shapes, not listed
  text "Layer" at 205.961,175.482 h1.52
  text "Name" at 216.372,175.482 h1.52
  text "Material" at 239.988,175.482 h1.52
  text "Thickness" at 261.826,175.482 h1.52
  text "Constant" at 278.332,175.482 h1.52
  text "Board Layer Stack" at 292.806,175.482 h1.52
  text "1" at 205.961,172.434 h1.52
  text "Top Overlay" at 216.372,172.434 h1.52
  text "2" at 205.961,169.386 h1.52
  text "Top Solder" at 216.372,169.386 h1.52
  text "Solder Resist" at 239.988,169.386 h1.52
  text "0.40mil" at 261.826,169.386 h1.52
  text "3.5" at 278.332,169.386 h1.52
  text "3" at 205.961,166.338 h1.52
  text "Top Layer" at 216.372,166.338 h1.52
  text "Copper" at 239.988,166.338 h1.52
  text "1.40mil" at 261.826,166.338 h1.52
  text "4" at 205.961,163.29 h1.52
  text "Dielectric1" at 216.372,163.29 h1.52
  text "FR-4" at 239.988,163.29 h1.52
  text "59.20mil" at 261.826,163.29 h1.52
  text "4.8" at 278.332,163.29 h1.52
  text "5" at 205.961,160.242 h1.52
  text "Bottom Layer" at 216.372,160.242 h1.52
  text "Copper" at 239.988,160.242 h1.52
  text "1.40mil" at 261.826,160.242 h1.52
  text "6" at 205.961,157.194 h1.52
  text "Bottom Solder" at 216.372,157.194 h1.52
  text "Solder Resist" at 239.988,157.194 h1.52
  text "0.40mil" at 261.826,157.194 h1.52
  text "3.5" at 278.332,157.194 h1.52
  text "7" at 205.961,154.146 h1.52
  text "Bottom Overlay" at 216.372,154.146 h1.52
  text ".Layer_Name" at -28.064,-45.206 h1.52
M13 Component Bodies Top:
  text ".Layer_Name" at -28.064,-45.206 h1.52
M14 Component Bodies Bottom:
  text ".Layer_Name" at -28.064,-45.206 h1.52
M15 Courtyards Top:
  text ".Layer_Name" at -28.064,-45.206 h1.52
M16 Courtyards Bottom:
  text ".Layer_Name" at -28.064,-45.206 h1.52
Drill Drawing:
  circle w0.025: c98.827,54.622 r0.632
  lines w0.025: 98.195,50.197 99.459,50.197 99.459,51.461 98.195,51.461 98.195,50.197 ; 98.195,59.047 99.459,59.047 98.827,57.782 98.195,59.047
  lines w0.305: 96.472,49.059 150.27,49.059 ; 96.472,60.437 150.27,60.437 ; 105.879,45.266 105.879,64.23 ; 114.947,45.266 114.947,64.23 ; 131.751,45.266 131.751,64.23 ; 138.968,45.266 138.968,64.23 ; 96.472,45.266 150.27,45.266 150.27,64.23 96.472,64.23 96.472,45.266
  text "Symbol" at 98.748,61.575 h1.83
  text "Quantity" at 107.017,61.575 h1.83
  text "Finished Hole Size" at 116.085,61.575 h1.83
  text "Plated" at 132.889,61.575 h1.83
  text "Hole Type" at 140.106,61.575 h1.83
  text "2" at 107.017,57.782 h1.52
  text "27.56mil (0.700mm)" at 116.085,57.782 h1.52
  text "PTH" at 132.889,57.782 h1.52
  text "Round" at 140.106,57.782 h1.52
  text "4" at 107.017,53.99 h1.52
  text "43.31mil (1.100mm)" at 116.085,53.99 h1.52
  text "PTH" at 132.889,53.99 h1.52
  text "Round" at 140.106,53.99 h1.52
  text "4" at 107.017,50.197 h1.52
  text "125.98mil (3.200mm)" at 116.085,50.197 h1.52
  text "PTH" at 132.889,50.197 h1.52
  text "Round" at 140.106,50.197 h1.52
  text "10 Total" at 107.017,46.404 h1.52
  text ".Layer_Name" at -28.064,-45.206 h1.52

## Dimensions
-42.72,-33.56 to -17.32,-33.56 on M2 Board Dimensions
-42.72,-23.4 to -42.72,64.23 on M2 Board Dimensions
-42.72,-23.4 to 83.01,-23.4 on M2 Board Dimensions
